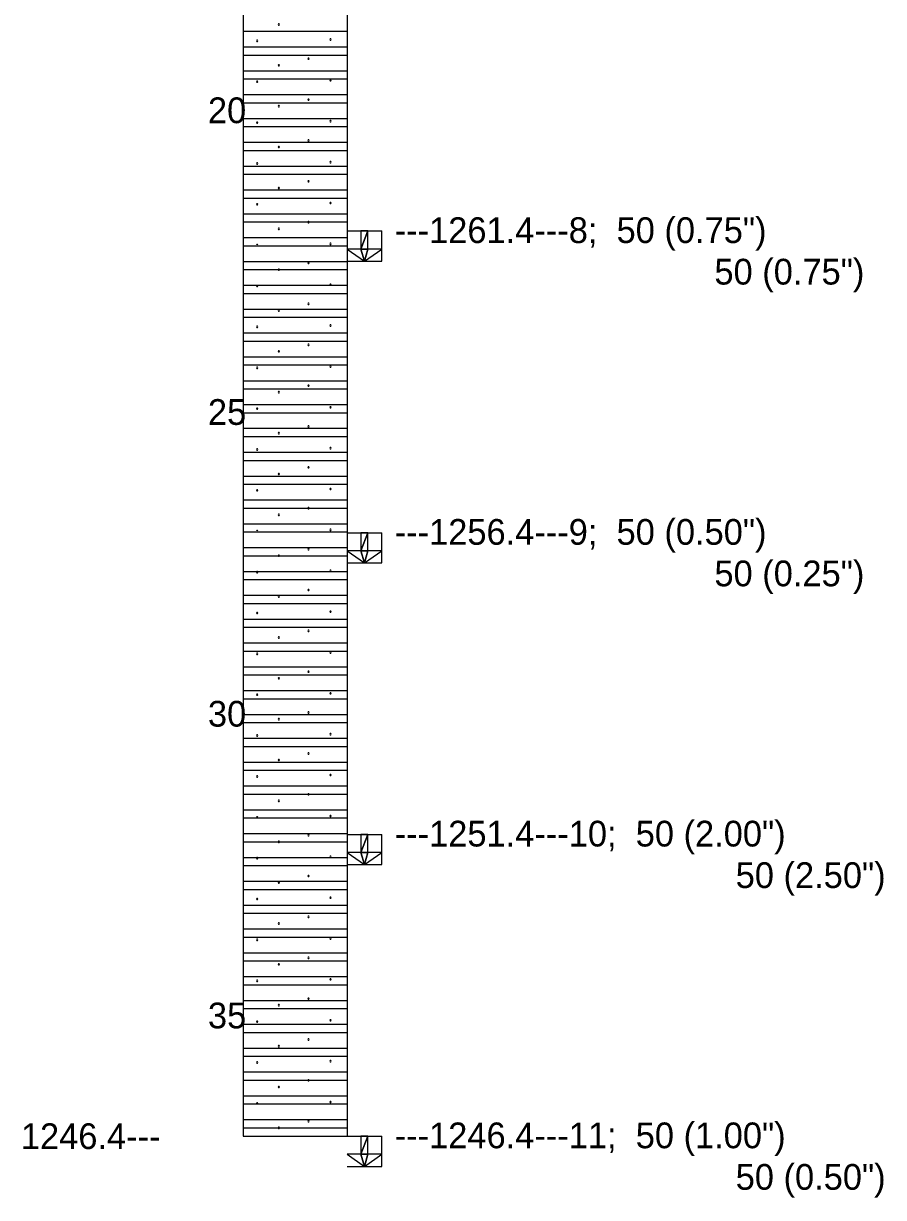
# Model space of a CAD drawing. Extents: x 7 to 126, y 24 to 56.
# Drawn here: x 59.48 to 63.63, y 38.79 to 44.45 of the extents above; entities that cross this region are included whole.
import ezdxf

# ---------------------------------------------------------------- set-up
doc = ezdxf.new("R2010")
doc.units = 0

msp = doc.modelspace()

# ---------------------------------------------------------------- linework, layer by layer
for points in [[(60.5434, 49.8418), (60.5434, 39.086)], [(61.0434, 49.8418), (61.0434, 39.086)], [(60.5434, 44.4085), (61.0434, 44.4085)], [(60.7185, 44.4412), (60.7169, 44.4441), (60.7136, 44.4441), (60.712, 44.4413), (60.7136, 44.4384), (60.7169, 44.4384), (60.7185, 44.4412)], [(60.6139, 44.3623), (60.6122, 44.3651), (60.6089, 44.3651), (60.6073, 44.3623), (60.6089, 44.3594), (60.6122, 44.3594), (60.6139, 44.3623)], [(60.9666, 44.3688), (60.965, 44.3717), (60.9617, 44.3717), (60.9601, 44.3688), (60.9617, 44.366), (60.965, 44.366), (60.9666, 44.3688)], [(60.5434, 44.333), (61.0434, 44.333)], [(60.5434, 44.2937), (61.0434, 44.2937)], [(60.7185, 44.2444), (60.7169, 44.2473), (60.7136, 44.2473), (60.712, 44.2445), (60.7136, 44.2416), (60.7169, 44.2416), (60.7185, 44.2444)], [(60.8611, 44.2763), (60.8595, 44.2791), (60.8562, 44.2791), (60.8545, 44.2763), (60.8562, 44.2735), (60.8595, 44.2735), (60.8611, 44.2763)], [(60.5434, 44.2182), (61.0434, 44.2182)], [(60.5434, 44.1788), (61.0434, 44.1788)], [(60.9666, 44.1719), (60.965, 44.1748), (60.9617, 44.1748), (60.9601, 44.1719), (60.9617, 44.1691), (60.965, 44.1691), (60.9666, 44.1719)], [(60.6139, 44.1655), (60.6122, 44.1683), (60.6089, 44.1683), (60.6073, 44.1655), (60.6089, 44.1626), (60.6122, 44.1626), (60.6139, 44.1655)], [(60.5434, 44.1034), (61.0434, 44.1034)], [(60.5434, 44.064), (61.0434, 44.064)], [(60.8611, 44.0794), (60.8595, 44.0822), (60.8562, 44.0822), (60.8545, 44.0794), (60.8562, 44.0766), (60.8595, 44.0766), (60.8611, 44.0794)], [(60.7185, 44.0475), (60.7169, 44.0504), (60.7136, 44.0504), (60.712, 44.0476), (60.7136, 44.0447), (60.7169, 44.0447), (60.7185, 44.0475)], [(60.5434, 43.9885), (61.0434, 43.9885)], [(60.5434, 43.9492), (61.0434, 43.9492)], [(60.6139, 43.9686), (60.6122, 43.9714), (60.6089, 43.9714), (60.6073, 43.9686), (60.6089, 43.9657), (60.6122, 43.9657), (60.6139, 43.9686)], [(60.9666, 43.9751), (60.965, 43.978), (60.9617, 43.978), (60.9601, 43.9751), (60.9617, 43.9723), (60.965, 43.9723), (60.9666, 43.9751)], [(60.5434, 43.8737), (61.0434, 43.8737)], [(60.5434, 43.8343), (61.0434, 43.8343)], [(60.7185, 43.8507), (60.7169, 43.8536), (60.7136, 43.8536), (60.712, 43.8508), (60.7136, 43.8479), (60.7169, 43.8479), (60.7185, 43.8507)], [(60.8611, 43.8826), (60.8595, 43.8854), (60.8562, 43.8854), (60.8545, 43.8826), (60.8562, 43.8798), (60.8595, 43.8798), (60.8611, 43.8826)], [(60.6139, 43.7718), (60.6122, 43.7746), (60.6089, 43.7746), (60.6073, 43.7718), (60.6089, 43.7689), (60.6122, 43.7689), (60.6139, 43.7718)], [(60.9666, 43.7782), (60.965, 43.7811), (60.9617, 43.7811), (60.9601, 43.7782), (60.9617, 43.7754), (60.965, 43.7754), (60.9666, 43.7782)], [(60.5434, 43.7589), (61.0434, 43.7589)], [(60.5434, 43.7195), (61.0434, 43.7195)], [(60.8611, 43.6857), (60.8595, 43.6885), (60.8562, 43.6885), (60.8545, 43.6857), (60.8562, 43.6829), (60.8595, 43.6829), (60.8611, 43.6857)], [(60.5434, 43.6441), (61.0434, 43.6441)], [(60.5434, 43.6047), (61.0434, 43.6047)], [(60.7185, 43.6538), (60.7169, 43.6567), (60.7136, 43.6567), (60.712, 43.6539), (60.7136, 43.651), (60.7169, 43.651), (60.7185, 43.6538)], [(60.6139, 43.5749), (60.6122, 43.5777), (60.6089, 43.5777), (60.6073, 43.5749), (60.6089, 43.572), (60.6122, 43.572), (60.6139, 43.5749)], [(60.9666, 43.5814), (60.965, 43.5843), (60.9617, 43.5843), (60.9601, 43.5814), (60.9617, 43.5786), (60.965, 43.5786), (60.9666, 43.5814)], [(60.5434, 43.5292), (61.0434, 43.5292)], [(60.8611, 43.4889), (60.8595, 43.4917), (60.8562, 43.4917), (60.8545, 43.4889), (60.8562, 43.4861), (60.8595, 43.4861), (60.8611, 43.4889)], [(60.5434, 43.4899), (61.0434, 43.4899)], [(60.7185, 43.457), (60.7169, 43.4599), (60.7136, 43.4599), (60.712, 43.4571), (60.7136, 43.4542), (60.7169, 43.4542), (60.7185, 43.457)], [(61.0434, 43.4464), (61.2101, 43.4464)], [(61.2101, 43.3011), (61.2101, 43.4464)], [(60.5434, 43.4144), (61.0434, 43.4144)], [(60.6139, 43.3781), (60.6122, 43.3809), (60.6089, 43.3809), (60.6073, 43.3781), (60.6089, 43.3752), (60.6122, 43.3752), (60.6139, 43.3781)], [(60.9666, 43.3845), (60.965, 43.3874), (60.9617, 43.3874), (60.9601, 43.3845), (60.9617, 43.3817), (60.965, 43.3817), (60.9666, 43.3845)], [(60.5434, 43.375), (61.0434, 43.375)], [(60.5434, 43.2996), (61.0434, 43.2996)], [(60.8611, 43.292), (60.8595, 43.2948), (60.8562, 43.2948), (60.8545, 43.292), (60.8562, 43.2892), (60.8595, 43.2892), (60.8611, 43.292)], [(61.0434, 43.3011), (61.2101, 43.3011)], [(60.5434, 43.2602), (61.0434, 43.2602)], [(60.7185, 43.2601), (60.7169, 43.263), (60.7136, 43.263), (60.712, 43.2602), (60.7136, 43.2573), (60.7169, 43.2573), (60.7185, 43.2601)], [(60.5434, 43.1847), (61.0434, 43.1847)], [(60.6139, 43.1812), (60.6122, 43.184), (60.6089, 43.184), (60.6073, 43.1812), (60.6089, 43.1783), (60.6122, 43.1783), (60.6139, 43.1812)], [(60.9666, 43.1877), (60.965, 43.1906), (60.9617, 43.1906), (60.9601, 43.1877), (60.9617, 43.1849), (60.965, 43.1849), (60.9666, 43.1877)], [(60.5434, 43.1454), (61.0434, 43.1454)], [(60.8611, 43.0952), (60.8595, 43.098), (60.8562, 43.098), (60.8545, 43.0952), (60.8562, 43.0924), (60.8595, 43.0924), (60.8611, 43.0952)], [(60.5434, 43.0699), (61.0434, 43.0699)], [(60.7185, 43.0633), (60.7169, 43.0662), (60.7136, 43.0662), (60.712, 43.0634), (60.7136, 43.0605), (60.7169, 43.0605), (60.7185, 43.0633)], [(60.5434, 43.0305), (61.0434, 43.0305)], [(60.6139, 42.9843), (60.6122, 42.9872), (60.6089, 42.9872), (60.6073, 42.9843), (60.6089, 42.9815), (60.6122, 42.9815), (60.6139, 42.9843)], [(60.9666, 42.9908), (60.965, 42.9937), (60.9617, 42.9937), (60.9601, 42.9908), (60.9617, 42.988), (60.965, 42.988), (60.9666, 42.9908)], [(60.5434, 42.9551), (61.0434, 42.9551)], [(60.5434, 42.9157), (61.0434, 42.9157)], [(60.7185, 42.8664), (60.7169, 42.8693), (60.7136, 42.8693), (60.712, 42.8665), (60.7136, 42.8636), (60.7169, 42.8636), (60.7185, 42.8664)], [(60.8611, 42.8983), (60.8595, 42.9011), (60.8562, 42.9011), (60.8545, 42.8983), (60.8562, 42.8955), (60.8595, 42.8955), (60.8611, 42.8983)], [(60.5434, 42.8403), (61.0434, 42.8403)], [(60.5434, 42.8009), (61.0434, 42.8009)], [(60.6139, 42.7875), (60.6122, 42.7903), (60.6089, 42.7903), (60.6073, 42.7875), (60.6089, 42.7846), (60.6122, 42.7846), (60.6139, 42.7875)], [(60.9666, 42.794), (60.965, 42.7969), (60.9617, 42.7969), (60.9601, 42.794), (60.9617, 42.7912), (60.965, 42.7912), (60.9666, 42.794)], [(60.5434, 42.7254), (61.0434, 42.7254)], [(60.8611, 42.7015), (60.8595, 42.7043), (60.8562, 42.7043), (60.8545, 42.7015), (60.8562, 42.6987), (60.8595, 42.6987), (60.8611, 42.7015)], [(60.5434, 42.6861), (61.0434, 42.6861)], [(60.7185, 42.6696), (60.7169, 42.6725), (60.7136, 42.6725), (60.712, 42.6697), (60.7136, 42.6668), (60.7169, 42.6668), (60.7185, 42.6696)], [(60.5434, 42.6106), (61.0434, 42.6106)], [(60.6139, 42.5906), (60.6122, 42.5935), (60.6089, 42.5935), (60.6073, 42.5906), (60.6089, 42.5878), (60.6122, 42.5878), (60.6139, 42.5906)], [(60.9666, 42.5971), (60.965, 42.6), (60.9617, 42.6), (60.9601, 42.5971), (60.9617, 42.5943), (60.965, 42.5943), (60.9666, 42.5971)], [(60.5434, 42.5712), (61.0434, 42.5712)], [(60.5434, 42.4958), (61.0434, 42.4958)], [(60.7185, 42.4727), (60.7169, 42.4756), (60.7136, 42.4756), (60.712, 42.4728), (60.7136, 42.4699), (60.7169, 42.4699), (60.7185, 42.4727)], [(60.8611, 42.5046), (60.8595, 42.5074), (60.8562, 42.5074), (60.8545, 42.5046), (60.8562, 42.5018), (60.8595, 42.5018), (60.8611, 42.5046)], [(60.5434, 42.4564), (61.0434, 42.4564)], [(60.5434, 42.3809), (61.0434, 42.3809)], [(60.6139, 42.3938), (60.6122, 42.3966), (60.6089, 42.3966), (60.6073, 42.3938), (60.6089, 42.3909), (60.6122, 42.3909), (60.6139, 42.3938)], [(60.9666, 42.4003), (60.965, 42.4032), (60.9617, 42.4032), (60.9601, 42.4003), (60.9617, 42.3975), (60.965, 42.3975), (60.9666, 42.4003)], [(60.5434, 42.3416), (61.0434, 42.3416)], [(60.8611, 42.3078), (60.8595, 42.3106), (60.8562, 42.3106), (60.8545, 42.3078), (60.8562, 42.305), (60.8595, 42.305), (60.8611, 42.3078)], [(60.5434, 42.2661), (61.0434, 42.2661)], [(60.7185, 42.2759), (60.7169, 42.2788), (60.7136, 42.2788), (60.712, 42.276), (60.7136, 42.2731), (60.7169, 42.2731), (60.7185, 42.2759)], [(60.5434, 42.2267), (61.0434, 42.2267)], [(60.6139, 42.1969), (60.6122, 42.1998), (60.6089, 42.1998), (60.6073, 42.1969), (60.6089, 42.1941), (60.6122, 42.1941), (60.6139, 42.1969)], [(60.9666, 42.2034), (60.965, 42.2063), (60.9617, 42.2063), (60.9601, 42.2034), (60.9617, 42.2006), (60.965, 42.2006), (60.9666, 42.2034)], [(60.5434, 42.1513), (61.0434, 42.1513)], [(60.5434, 42.1119), (61.0434, 42.1119)], [(60.7185, 42.079), (60.7169, 42.0819), (60.7136, 42.0819), (60.712, 42.0791), (60.7136, 42.0762), (60.7169, 42.0762), (60.7185, 42.079)], [(60.8611, 42.1109), (60.8595, 42.1137), (60.8562, 42.1137), (60.8545, 42.1109), (60.8562, 42.1081), (60.8595, 42.1081), (60.8611, 42.1109)], [(60.5434, 42.0364), (61.0434, 42.0364)], [(60.5434, 41.9971), (61.0434, 41.9971)], [(60.6139, 42.0001), (60.6122, 42.0029), (60.6089, 42.0029), (60.6073, 42.0001), (60.6089, 41.9972), (60.6122, 41.9972), (60.6139, 42.0001)], [(60.9666, 42.0066), (60.965, 42.0095), (60.9617, 42.0095), (60.9601, 42.0066), (60.9617, 42.0038), (60.965, 42.0038), (60.9666, 42.0066)], [(61.0434, 41.993), (61.2101, 41.993)], [(61.2101, 41.8476), (61.2101, 41.993)], [(60.5434, 41.9216), (61.0434, 41.9216)], [(60.8611, 41.9141), (60.8595, 41.9169), (60.8562, 41.9169), (60.8545, 41.9141), (60.8562, 41.9113), (60.8595, 41.9113), (60.8611, 41.9141)], [(60.5434, 41.8822), (61.0434, 41.8822)], [(60.7185, 41.8822), (60.7169, 41.8851), (60.7136, 41.8851), (60.712, 41.8822), (60.7136, 41.8794), (60.7169, 41.8794), (60.7185, 41.8822)], [(60.5434, 41.8068), (61.0434, 41.8068)], [(60.6139, 41.8032), (60.6122, 41.8061), (60.6089, 41.8061), (60.6073, 41.8032), (60.6089, 41.8004), (60.6122, 41.8004), (60.6139, 41.8032)], [(60.9666, 41.8097), (60.965, 41.8126), (60.9617, 41.8126), (60.9601, 41.8097), (60.9617, 41.8069), (60.965, 41.8069), (60.9666, 41.8097)], [(61.0434, 41.8476), (61.2101, 41.8476)], [(60.5434, 41.7674), (61.0434, 41.7674)], [(60.5434, 41.692), (61.0434, 41.692)], [(60.7185, 41.6853), (60.7169, 41.6882), (60.7136, 41.6882), (60.712, 41.6854), (60.7136, 41.6825), (60.7169, 41.6825), (60.7185, 41.6853)], [(60.8611, 41.7172), (60.8595, 41.72), (60.8562, 41.72), (60.8545, 41.7172), (60.8562, 41.7144), (60.8595, 41.7144), (60.8611, 41.7172)], [(60.5434, 41.6526), (61.0434, 41.6526)], [(60.5434, 41.5771), (61.0434, 41.5771)], [(60.6139, 41.6064), (60.6122, 41.6092), (60.6089, 41.6092), (60.6073, 41.6064), (60.6089, 41.6035), (60.6122, 41.6035), (60.6139, 41.6064)], [(60.9666, 41.6129), (60.965, 41.6158), (60.9617, 41.6158), (60.9601, 41.6129), (60.9617, 41.6101), (60.965, 41.6101), (60.9666, 41.6129)], [(60.5434, 41.5378), (61.0434, 41.5378)], [(60.8611, 41.5204), (60.8595, 41.5232), (60.8562, 41.5232), (60.8545, 41.5204), (60.8562, 41.5176), (60.8595, 41.5176), (60.8611, 41.5204)], [(60.5434, 41.4623), (61.0434, 41.4623)], [(60.7185, 41.4885), (60.7169, 41.4914), (60.7136, 41.4914), (60.712, 41.4885), (60.7136, 41.4857), (60.7169, 41.4857), (60.7185, 41.4885)], [(60.5434, 41.4229), (61.0434, 41.4229)], [(60.6139, 41.4095), (60.6122, 41.4124), (60.6089, 41.4124), (60.6073, 41.4095), (60.6089, 41.4067), (60.6122, 41.4067), (60.6139, 41.4095)], [(60.9666, 41.416), (60.965, 41.4189), (60.9617, 41.4189), (60.9601, 41.416), (60.9617, 41.4132), (60.965, 41.4132), (60.9666, 41.416)], [(60.5434, 41.3475), (61.0434, 41.3475)], [(60.5434, 41.3081), (61.0434, 41.3081)], [(60.7185, 41.2916), (60.7169, 41.2945), (60.7136, 41.2945), (60.712, 41.2917), (60.7136, 41.2888), (60.7169, 41.2888), (60.7185, 41.2916)], [(60.8611, 41.3235), (60.8595, 41.3263), (60.8562, 41.3263), (60.8545, 41.3235), (60.8562, 41.3207), (60.8595, 41.3207), (60.8611, 41.3235)], [(60.5434, 41.2326), (61.0434, 41.2326)], [(60.5434, 41.1933), (61.0434, 41.1933)], [(60.6139, 41.2127), (60.6122, 41.2155), (60.6089, 41.2155), (60.6073, 41.2127), (60.6089, 41.2098), (60.6122, 41.2098), (60.6139, 41.2127)], [(60.9666, 41.2192), (60.965, 41.2221), (60.9617, 41.2221), (60.9601, 41.2192), (60.9617, 41.2164), (60.965, 41.2164), (60.9666, 41.2192)], [(60.5434, 41.1178), (61.0434, 41.1178)], [(60.8611, 41.1267), (60.8595, 41.1295), (60.8562, 41.1295), (60.8545, 41.1267), (60.8562, 41.1239), (60.8595, 41.1239), (60.8611, 41.1267)], [(60.5434, 41.0784), (61.0434, 41.0784)], [(60.7185, 41.0948), (60.7169, 41.0977), (60.7136, 41.0977), (60.712, 41.0948), (60.7136, 41.092), (60.7169, 41.092), (60.7185, 41.0948)], [(60.5434, 41.003), (61.0434, 41.003)], [(60.6139, 41.0158), (60.6122, 41.0187), (60.6089, 41.0187), (60.6073, 41.0158), (60.6089, 41.013), (60.6122, 41.013), (60.6139, 41.0158)], [(60.9666, 41.0223), (60.965, 41.0252), (60.9617, 41.0252), (60.9601, 41.0223), (60.9617, 41.0195), (60.965, 41.0195), (60.9666, 41.0223)], [(60.5434, 40.9636), (61.0434, 40.9636)], [(60.7185, 40.8979), (60.7169, 40.9008), (60.7136, 40.9008), (60.712, 40.898), (60.7136, 40.8951), (60.7169, 40.8951), (60.7185, 40.8979)], [(60.8611, 40.9298), (60.8595, 40.9326), (60.8562, 40.9326), (60.8545, 40.9298), (60.8562, 40.927), (60.8595, 40.927), (60.8611, 40.9298)], [(60.5434, 40.8882), (61.0434, 40.8882)], [(60.5434, 40.8488), (61.0434, 40.8488)], [(60.6139, 40.819), (60.6122, 40.8218), (60.6089, 40.8218), (60.6073, 40.819), (60.6089, 40.8161), (60.6122, 40.8161), (60.6139, 40.819)], [(60.9666, 40.8255), (60.965, 40.8284), (60.9617, 40.8284), (60.9601, 40.8255), (60.9617, 40.8227), (60.965, 40.8227), (60.9666, 40.8255)], [(60.5434, 40.7733), (61.0434, 40.7733)], [(60.5434, 40.734), (61.0434, 40.734)], [(60.8611, 40.733), (60.8595, 40.7358), (60.8562, 40.7358), (60.8545, 40.733), (60.8562, 40.7301), (60.8595, 40.7301), (60.8611, 40.733)], [(60.7185, 40.7011), (60.7169, 40.704), (60.7136, 40.704), (60.712, 40.7011), (60.7136, 40.6983), (60.7169, 40.6983), (60.7185, 40.7011)], [(60.5434, 40.6585), (61.0434, 40.6585)], [(60.5434, 40.6191), (61.0434, 40.6191)], [(60.6139, 40.6221), (60.6122, 40.625), (60.6089, 40.625), (60.6073, 40.6221), (60.6089, 40.6193), (60.6122, 40.6193), (60.6139, 40.6221)], [(60.9666, 40.6286), (60.965, 40.6315), (60.9617, 40.6315), (60.9601, 40.6286), (60.9617, 40.6258), (60.965, 40.6258), (60.9666, 40.6286)], [(60.5434, 40.5437), (61.0434, 40.5437)], [(60.5434, 40.5043), (61.0434, 40.5043)], [(60.7185, 40.5042), (60.7169, 40.5071), (60.7136, 40.5071), (60.712, 40.5043), (60.7136, 40.5014), (60.7169, 40.5014), (60.7185, 40.5042)], [(60.8611, 40.5361), (60.8595, 40.5389), (60.8562, 40.5389), (60.8545, 40.5361), (60.8562, 40.5333), (60.8595, 40.5333), (60.8611, 40.5361)], [(61.0434, 40.5395), (61.2101, 40.5395)], [(61.2101, 40.3941), (61.2101, 40.5395)], [(60.5434, 40.4288), (61.0434, 40.4288)], [(60.5434, 40.3895), (61.0434, 40.3895)], [(60.6139, 40.4253), (60.6122, 40.4281), (60.6089, 40.4281), (60.6073, 40.4253), (60.6089, 40.4224), (60.6122, 40.4224), (60.6139, 40.4253)], [(60.9666, 40.4318), (60.965, 40.4347), (60.9617, 40.4347), (60.9601, 40.4318), (60.9617, 40.429), (60.965, 40.429), (60.9666, 40.4318)], [(61.0434, 40.3941), (61.2101, 40.3941)], [(60.8611, 40.3393), (60.8595, 40.3421), (60.8562, 40.3421), (60.8545, 40.3393), (60.8562, 40.3364), (60.8595, 40.3364), (60.8611, 40.3393)], [(60.5434, 40.314), (61.0434, 40.314)], [(60.5434, 40.2746), (61.0434, 40.2746)], [(60.7185, 40.3074), (60.7169, 40.3103), (60.7136, 40.3103), (60.712, 40.3074), (60.7136, 40.3046), (60.7169, 40.3046), (60.7185, 40.3074)], [(60.6139, 40.2284), (60.6122, 40.2313), (60.6089, 40.2313), (60.6073, 40.2284), (60.6089, 40.2256), (60.6122, 40.2256), (60.6139, 40.2284)], [(60.9666, 40.2349), (60.965, 40.2378), (60.9617, 40.2378), (60.9601, 40.2349), (60.9617, 40.2321), (60.965, 40.2321), (60.9666, 40.2349)], [(60.5434, 40.1992), (61.0434, 40.1992)], [(60.5434, 40.1598), (61.0434, 40.1598)], [(60.7185, 40.1105), (60.7169, 40.1134), (60.7136, 40.1134), (60.712, 40.1106), (60.7136, 40.1077), (60.7169, 40.1077), (60.7185, 40.1105)], [(60.8611, 40.1424), (60.8595, 40.1452), (60.8562, 40.1452), (60.8545, 40.1424), (60.8562, 40.1396), (60.8595, 40.1396), (60.8611, 40.1424)], [(60.5434, 40.0843), (61.0434, 40.0843)], [(60.5434, 40.045), (61.0434, 40.045)], [(60.9666, 40.0381), (60.965, 40.041), (60.9617, 40.041), (60.9601, 40.0381), (60.9617, 40.0353), (60.965, 40.0353), (60.9666, 40.0381)], [(60.6139, 40.0316), (60.6122, 40.0344), (60.6089, 40.0344), (60.6073, 40.0316), (60.6089, 40.0287), (60.6122, 40.0287), (60.6139, 40.0316)], [(60.5434, 39.9695), (61.0434, 39.9695)], [(60.5434, 39.9301), (61.0434, 39.9301)], [(60.8611, 39.9456), (60.8595, 39.9484), (60.8562, 39.9484), (60.8545, 39.9456), (60.8562, 39.9427), (60.8595, 39.9427), (60.8611, 39.9456)], [(60.7185, 39.9137), (60.7169, 39.9166), (60.7136, 39.9166), (60.712, 39.9137), (60.7136, 39.9109), (60.7169, 39.9109), (60.7185, 39.9137)], [(60.5434, 39.8547), (61.0434, 39.8547)], [(60.5434, 39.8153), (61.0434, 39.8153)], [(60.6139, 39.8347), (60.6122, 39.8376), (60.6089, 39.8376), (60.6073, 39.8347), (60.6089, 39.8319), (60.6122, 39.8319), (60.6139, 39.8347)], [(60.9666, 39.8412), (60.965, 39.8441), (60.9617, 39.8441), (60.9601, 39.8412), (60.9617, 39.8384), (60.965, 39.8384), (60.9666, 39.8412)], [(60.5434, 39.7399), (61.0434, 39.7399)], [(60.7185, 39.7168), (60.7169, 39.7197), (60.7136, 39.7197), (60.712, 39.7169), (60.7136, 39.714), (60.7169, 39.714), (60.7185, 39.7168)], [(60.8611, 39.7487), (60.8595, 39.7515), (60.8562, 39.7515), (60.8545, 39.7487), (60.8562, 39.7459), (60.8595, 39.7459), (60.8611, 39.7487)], [(60.5434, 39.7005), (61.0434, 39.7005)], [(60.9666, 39.6444), (60.965, 39.6473), (60.9617, 39.6473), (60.9601, 39.6444), (60.9617, 39.6416), (60.965, 39.6416), (60.9666, 39.6444)], [(60.5434, 39.625), (61.0434, 39.625)], [(60.6139, 39.6379), (60.6122, 39.6407), (60.6089, 39.6407), (60.6073, 39.6379), (60.6089, 39.635), (60.6122, 39.635), (60.6139, 39.6379)], [(60.5434, 39.5857), (61.0434, 39.5857)], [(60.8611, 39.5519), (60.8595, 39.5547), (60.8562, 39.5547), (60.8545, 39.5519), (60.8562, 39.549), (60.8595, 39.549), (60.8611, 39.5519)], [(60.5434, 39.5102), (61.0434, 39.5102)], [(60.7185, 39.52), (60.7169, 39.5229), (60.7136, 39.5229), (60.712, 39.52), (60.7136, 39.5172), (60.7169, 39.5172), (60.7185, 39.52)], [(60.5434, 39.4708), (61.0434, 39.4708)], [(60.6139, 39.441), (60.6122, 39.4439), (60.6089, 39.4439), (60.6073, 39.441), (60.6089, 39.4382), (60.6122, 39.4382), (60.6139, 39.441)], [(60.9666, 39.4475), (60.965, 39.4504), (60.9617, 39.4504), (60.9601, 39.4475), (60.9617, 39.4447), (60.965, 39.4447), (60.9666, 39.4475)], [(60.5434, 39.3954), (61.0434, 39.3954)], [(60.5434, 39.356), (61.0434, 39.356)], [(60.7185, 39.3231), (60.7169, 39.326), (60.7136, 39.326), (60.712, 39.3232), (60.7136, 39.3203), (60.7169, 39.3203), (60.7185, 39.3231)], [(60.8611, 39.355), (60.8595, 39.3578), (60.8562, 39.3578), (60.8545, 39.355), (60.8562, 39.3522), (60.8595, 39.3522), (60.8611, 39.355)], [(60.5434, 39.2805), (61.0434, 39.2805)], [(60.9666, 39.2507), (60.965, 39.2536), (60.9617, 39.2536), (60.9601, 39.2507), (60.9617, 39.2479), (60.965, 39.2479), (60.9666, 39.2507)], [(60.5434, 39.2412), (61.0434, 39.2412)], [(60.6139, 39.2442), (60.6122, 39.247), (60.6089, 39.247), (60.6073, 39.2442), (60.6089, 39.2413), (60.6122, 39.2413), (60.6139, 39.2442)], [(60.5434, 39.1657), (61.0434, 39.1657)], [(60.8611, 39.1582), (60.8595, 39.161), (60.8562, 39.161), (60.8545, 39.1582), (60.8562, 39.1553), (60.8595, 39.1553), (60.8611, 39.1582)], [(60.5434, 39.1263), (61.0434, 39.1263)], [(60.5434, 39.086), (61.0434, 39.086)], [(60.7185, 39.1263), (60.7169, 39.1292), (60.7136, 39.1292), (60.712, 39.1263), (60.7136, 39.1235), (60.7169, 39.1235), (60.7185, 39.1263)], [(61.0434, 39.086), (61.2101, 39.086)], [(61.2101, 38.9406), (61.2101, 39.086)], [(61.0434, 38.9406), (61.2101, 38.9406)]]:
    msp.add_lwpolyline(points)
for points in [[(61.1101, 43.3592), (61.1434, 43.3592), (61.1434, 43.4464), (61.1101, 43.3592)], [(61.1101, 43.3592), (61.1434, 43.4464), (61.1101, 43.4464), (61.1101, 43.3592)], [(61.1101, 43.3592), (61.0434, 43.3592), (61.1268, 43.3011), (61.1101, 43.3592)], [(61.1101, 43.3592), (61.1268, 43.3011), (61.1434, 43.3592), (61.1101, 43.3592)], [(61.1268, 43.3011), (61.2101, 43.3592), (61.1434, 43.3592), (61.1268, 43.3011)], [(61.1101, 41.9057), (61.1434, 41.9057), (61.1434, 41.993), (61.1101, 41.9057)], [(61.1101, 41.9057), (61.1434, 41.993), (61.1101, 41.993), (61.1101, 41.9057)], [(61.1101, 41.9057), (61.0434, 41.9057), (61.1268, 41.8476), (61.1101, 41.9057)], [(61.1101, 41.9057), (61.1268, 41.8476), (61.1434, 41.9057), (61.1101, 41.9057)], [(61.1268, 41.8476), (61.2101, 41.9057), (61.1434, 41.9057), (61.1268, 41.8476)], [(61.1101, 40.4523), (61.1434, 40.4523), (61.1434, 40.5395), (61.1101, 40.4523)], [(61.1101, 40.4523), (61.1434, 40.5395), (61.1101, 40.5395), (61.1101, 40.4523)], [(61.1101, 40.4523), (61.0434, 40.4523), (61.1268, 40.3941), (61.1101, 40.4523)], [(61.1101, 40.4523), (61.1268, 40.3941), (61.1434, 40.4523), (61.1101, 40.4523)], [(61.1268, 40.3941), (61.2101, 40.4523), (61.1434, 40.4523), (61.1268, 40.3941)], [(61.1101, 38.9988), (61.1434, 38.9988), (61.1434, 39.086), (61.1101, 38.9988)], [(61.1101, 38.9988), (61.1434, 39.086), (61.1101, 39.086), (61.1101, 38.9988)], [(61.1101, 38.9988), (61.0434, 38.9988), (61.1268, 38.9406), (61.1101, 38.9988)], [(61.1101, 38.9988), (61.1268, 38.9406), (61.1434, 38.9988), (61.1101, 38.9988)], [(61.1268, 38.9406), (61.2101, 38.9988), (61.1434, 38.9988), (61.1268, 38.9406)]]:
    msp.add_lwpolyline(points, close=True)

# ---------------------------------------------------------------- texts
for s, p in [('20', (60.373, 43.9658)), ('---1261.4---8;  50 (0.75")', (61.2727, 43.3884)), ('50 (0.75")', (62.813, 43.1884)), ('25', (60.373, 42.5124)), ('---1256.4---9;  50 (0.50")', (61.2727, 41.9349)), ('50 (0.25")', (62.813, 41.7349)), ('30', (60.373, 41.0589)), ('---1251.4---10;  50 (2.00")', (61.2727, 40.4814)), ('50 (2.50")', (62.9154, 40.2814)), ('35', (60.373, 39.6054)), ('1246.4---', (59.4718, 39.024)), ('---1246.4---11;  50 (1.00")', (61.2727, 39.0279)), ('50 (0.50")', (62.9154, 38.8279))]:
    msp.add_text(s, height=0.124).set_placement(p)

doc.saveas('drawing.dxf')
